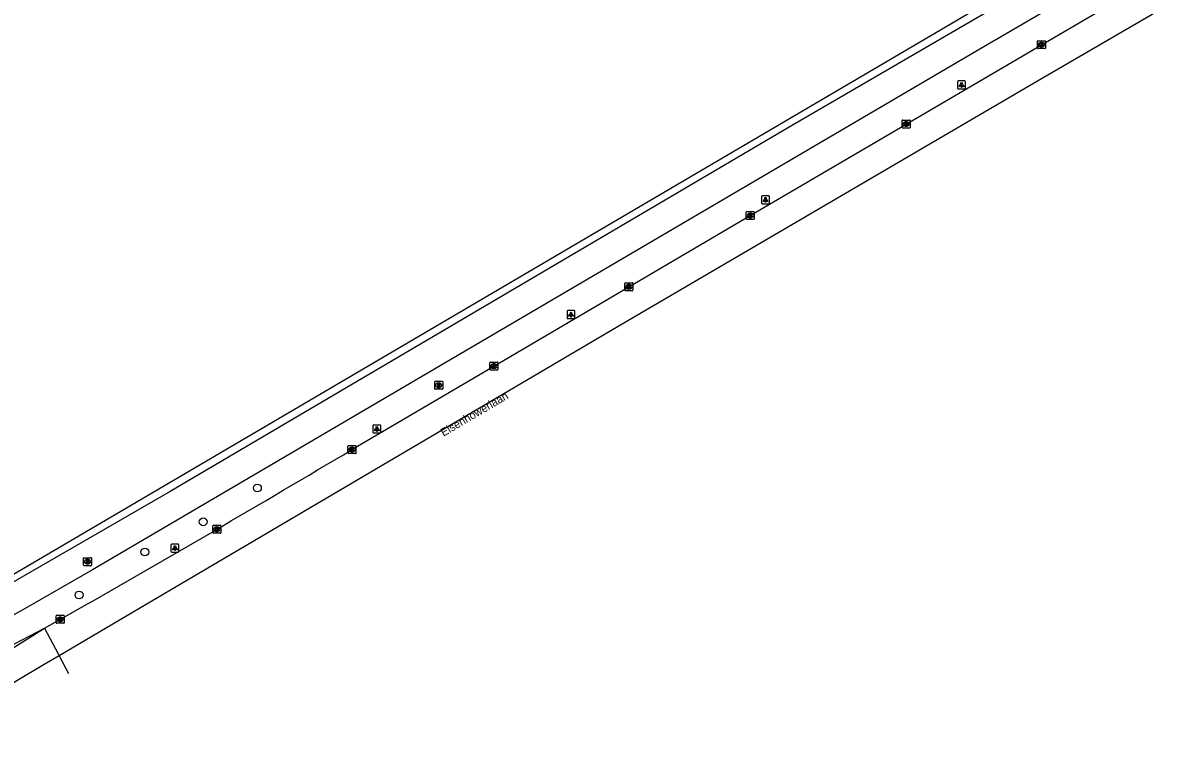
# Model space of a CAD drawing. Extents: x 162417 to 163721, y 384268 to 385416.
# Drawn here: x 163118.6 to 163261.1, y 384365.7 to 384458 of the extents above; entities that cross this region are included whole.
import ezdxf

# ---------------------------------------------------------------- set-up
doc = ezdxf.new("R2010")
doc.units = 0
for name, color, linetype in [('IMGEO_Berm_groen', 7, 'Continuous'), ('IMGEO_Boom', 7, 'Continuous'), ('IMGEO_Fietspad_gesloten', 7, 'Continuous'), ('IMGEO_Hek', 7, 'Continuous'), ('IMGEO_Kolk', 7, 'Continuous'), ('IMGEO_Lichtpunt', 7, 'Continuous'), ('IMGEO_Openbare_ruimte_label', 7, 'Continuous'), ('IMGEO_Rijbaan_regionaal_gesloten', 7, 'Continuous'), ('IMGEO_Rioolput', 7, 'Continuous')]:
    doc.layers.add(name, color=color, linetype=linetype)

msp = doc.modelspace()

# ---------------------------------------------------------------- linework, layer by layer
at = {"layer": 'IMGEO_Berm_groen'}
msp.add_lwpolyline([(163258.75, 384472.14), (163115.25, 384387.77)], dxfattribs=at)
at = {"layer": 'IMGEO_Boom'}
for centre in [(163147.88, 384399.86), (163141.11, 384395.62), (163133.82, 384391.85), (163125.6, 384386.48)]:
    msp.add_circle(centre, 0.489, dxfattribs=at)
at = {"layer": 'IMGEO_Fietspad_gesloten'}
for points in [[(163563.61, 384641.94), (163546.21, 384631.66), (163524.74, 384619.5), (163513.73, 384613.26), (163500, 384605.49), (163486.44, 384597.82), (163417.72, 384558.76), (163354.58, 384522.52), (163336.98, 384512.3), (163315.8, 384500), (163237.63, 384454.43), (163127.28, 384389.63), (163118.59, 384384.62), (163112.28, 384381.2), (163106.55, 384378.4)], [(163345.85, 384521.53), (163335.19, 384515.32), (163308.87, 384500), (163214.31, 384444.96), (163137, 384399.43), (163115.64, 384387.12)]]:
    msp.add_lwpolyline(points, dxfattribs=at)
at = {"layer": 'IMGEO_Hek'}
msp.add_lwpolyline([(163258.75, 384472.14), (163115.25, 384387.77)], dxfattribs=at)
at = {"layer": 'IMGEO_Kolk'}
for p, q in [((163245.34, 384454.86), (163245.34, 384455.71)), ((163245.41, 384455.78), (163246.27, 384455.78)), ((163245.83, 384455.56), (163245.85, 384455.56)), ((163245.85, 384455), (163245.83, 384455)), ((163246.34, 384455.71), (163246.34, 384454.86)), ((163246.27, 384454.78), (163245.41, 384454.78)), ((163228.44, 384444.93), (163228.44, 384445.79)), ((163228.52, 384445.86), (163229.37, 384445.86)), ((163229.37, 384444.86), (163228.52, 384444.86)), ((163228.93, 384445.64), (163228.96, 384445.64)), ((163228.95, 384445.08), (163228.93, 384445.08)), ((163229.44, 384445.79), (163229.44, 384444.93)), ((163208.97, 384433.49), (163208.97, 384434.35)), ((163209.04, 384434.42), (163209.9, 384434.42)), ((163209.9, 384433.42), (163209.04, 384433.42)), ((163209.48, 384433.64), (163209.45, 384433.64)), ((163209.46, 384434.2), (163209.48, 384434.2)), ((163209.97, 384434.35), (163209.97, 384433.49)), ((163193.79, 384424.59), (163193.79, 384425.44)), ((163193.87, 384425.52), (163194.72, 384425.52)), ((163194.28, 384425.29), (163194.31, 384425.29)), ((163194.8, 384425.44), (163194.8, 384424.59)), ((163194.72, 384424.51), (163193.87, 384424.51)), ((163194.3, 384424.74), (163194.28, 384424.74)), ((163176.93, 384414.67), (163176.93, 384415.52)), ((163177, 384415.59), (163177.85, 384415.59)), ((163177.42, 384415.37), (163177.44, 384415.37)), ((163177.93, 384415.52), (163177.93, 384414.67)), ((163177.85, 384414.59), (163177, 384414.59)), ((163177.44, 384414.81), (163177.41, 384414.81)), ((163159.2, 384404.23), (163159.2, 384405.09)), ((163159.28, 384405.16), (163160.13, 384405.16)), ((163159.69, 384404.94), (163159.71, 384404.94)), ((163160.2, 384405.09), (163160.2, 384404.23)), ((163160.13, 384404.16), (163159.28, 384404.16)), ((163159.71, 384404.38), (163159.69, 384404.38)), ((163142.31, 384394.27), (163142.31, 384395.13)), ((163142.39, 384395.2), (163143.24, 384395.2)), ((163142.8, 384394.98), (163142.83, 384394.98)), ((163143.31, 384395.13), (163143.31, 384394.27)), ((163143.24, 384394.2), (163142.39, 384394.2)), ((163142.82, 384394.42), (163142.8, 384394.42)), ((163122.73, 384383.01), (163122.73, 384383.87)), ((163122.81, 384383.94), (163123.66, 384383.94)), ((163123.22, 384383.72), (163123.25, 384383.72)), ((163123.74, 384383.87), (163123.74, 384383.01)), ((163123.66, 384382.94), (163122.81, 384382.94)), ((163123.24, 384383.16), (163123.22, 384383.16))]:
    msp.add_line(p, q, dxfattribs=at)
for points in [[(163245.34, 384454.86), (163245.34, 384455.71)], [(163245.41, 384455.78), (163246.27, 384455.78)], [(163245.66, 384455.48), (163245.78, 384455.48), (163245.78, 384455.33), (163245.91, 384455.48), (163246.08, 384455.48), (163245.93, 384455.33), (163246.08, 384455.08), (163245.93, 384455.08), (163245.85, 384455.25), (163245.78, 384455.18), (163245.78, 384455.08), (163245.66, 384455.08), (163245.66, 384455.48)], [(163246.34, 384455.71), (163246.34, 384454.86)], [(163246.27, 384454.78), (163245.41, 384454.78)], [(163228.44, 384444.93), (163228.44, 384445.79)], [(163228.52, 384445.86), (163229.37, 384445.86)], [(163229.37, 384444.86), (163228.52, 384444.86)], [(163228.76, 384445.56), (163228.89, 384445.56), (163228.89, 384445.41), (163229.02, 384445.56), (163229.18, 384445.56), (163229.03, 384445.41), (163229.19, 384445.16), (163229.03, 384445.16), (163228.95, 384445.32), (163228.89, 384445.26), (163228.89, 384445.16), (163228.76, 384445.16), (163228.76, 384445.56)], [(163229.44, 384445.79), (163229.44, 384444.93)], [(163208.97, 384433.49), (163208.97, 384434.35)], [(163209.04, 384434.42), (163209.9, 384434.42)], [(163209.9, 384433.42), (163209.04, 384433.42)], [(163209.29, 384434.12), (163209.41, 384434.12), (163209.41, 384433.97), (163209.54, 384434.12), (163209.71, 384434.12), (163209.56, 384433.97), (163209.71, 384433.72), (163209.56, 384433.72), (163209.48, 384433.88), (163209.41, 384433.82), (163209.41, 384433.72), (163209.29, 384433.72), (163209.29, 384434.12)], [(163209.97, 384434.35), (163209.97, 384433.49)], [(163193.79, 384424.59), (163193.79, 384425.44)], [(163193.87, 384425.52), (163194.72, 384425.52)], [(163194.11, 384425.21), (163194.24, 384425.21), (163194.24, 384425.06), (163194.37, 384425.21), (163194.53, 384425.21), (163194.39, 384425.06), (163194.54, 384424.81), (163194.39, 384424.81), (163194.3, 384424.98), (163194.24, 384424.91), (163194.24, 384424.81), (163194.11, 384424.81), (163194.11, 384425.21)], [(163194.8, 384425.44), (163194.8, 384424.59)], [(163194.72, 384424.51), (163193.87, 384424.51)], [(163176.93, 384414.67), (163176.93, 384415.52)], [(163177, 384415.59), (163177.85, 384415.59)], [(163177.25, 384415.29), (163177.37, 384415.29), (163177.37, 384415.14), (163177.5, 384415.29), (163177.67, 384415.29), (163177.52, 384415.14), (163177.67, 384414.89), (163177.52, 384414.89), (163177.44, 384415.06), (163177.37, 384414.99), (163177.37, 384414.89), (163177.25, 384414.89), (163177.25, 384415.29)], [(163177.93, 384415.52), (163177.93, 384414.67)], [(163177.85, 384414.59), (163177, 384414.59)], [(163159.2, 384404.23), (163159.2, 384405.09)], [(163159.28, 384405.16), (163160.13, 384405.16)], [(163160.2, 384405.09), (163160.2, 384404.23)], [(163160.13, 384404.16), (163159.28, 384404.16)], [(163159.52, 384404.86), (163159.65, 384404.86), (163159.65, 384404.71), (163159.77, 384404.86), (163159.94, 384404.86), (163159.79, 384404.71), (163159.95, 384404.46), (163159.79, 384404.46), (163159.71, 384404.62), (163159.65, 384404.56), (163159.65, 384404.46), (163159.52, 384404.46), (163159.52, 384404.86)], [(163142.31, 384394.27), (163142.31, 384395.13)], [(163142.39, 384395.2), (163143.24, 384395.2)], [(163143.31, 384395.13), (163143.31, 384394.27)], [(163143.24, 384394.2), (163142.39, 384394.2)], [(163142.63, 384394.9), (163142.76, 384394.9), (163142.76, 384394.75), (163142.89, 384394.9), (163143.05, 384394.9), (163142.91, 384394.75), (163143.06, 384394.5), (163142.91, 384394.5), (163142.82, 384394.67), (163142.76, 384394.6), (163142.76, 384394.5), (163142.63, 384394.5), (163142.63, 384394.9)], [(163122.73, 384383.01), (163122.73, 384383.87)], [(163122.81, 384383.94), (163123.66, 384383.94)], [(163123.05, 384383.64), (163123.18, 384383.64), (163123.18, 384383.49), (163123.31, 384383.64), (163123.47, 384383.64), (163123.33, 384383.49), (163123.48, 384383.24), (163123.33, 384383.24), (163123.24, 384383.41), (163123.18, 384383.34), (163123.18, 384383.24), (163123.05, 384383.24), (163123.05, 384383.64)], [(163123.74, 384383.87), (163123.74, 384383.01)], [(163123.66, 384382.94), (163122.81, 384382.94)]]:
    msp.add_lwpolyline(points, dxfattribs=at)
for centre, start, end in [((163245.42, 384455.71), 91.552, 178.448), ((163245.42, 384455.71), 91.552, 178.448), ((163245.42, 384454.86), 181.552, 268.448), ((163245.42, 384454.86), 181.552, 268.448), ((163246.26, 384455.71), 1.552, 88.448), ((163246.26, 384455.71), 1.552, 88.448), ((163246.26, 384454.86), 271.552, 358.448), ((163246.26, 384454.86), 271.552, 358.448), ((163228.52, 384445.78), 91.552, 178.448), ((163228.52, 384445.78), 91.552, 178.448), ((163228.52, 384444.94), 181.552, 268.448), ((163228.52, 384444.94), 181.552, 268.448), ((163229.37, 384445.78), 1.552, 88.448), ((163229.37, 384445.78), 1.552, 88.448), ((163229.37, 384444.94), 271.552, 358.448), ((163229.37, 384444.94), 271.552, 358.448), ((163209.04, 384434.34), 91.552, 178.448), ((163209.04, 384434.34), 91.552, 178.448), ((163209.04, 384433.5), 181.552, 268.448), ((163209.04, 384433.5), 181.552, 268.448), ((163209.89, 384434.34), 1.552, 88.448), ((163209.89, 384434.34), 1.552, 88.448), ((163209.89, 384433.5), 271.552, 358.448), ((163209.89, 384433.5), 271.552, 358.448), ((163193.87, 384425.44), 91.552, 178.448), ((163193.87, 384425.44), 91.552, 178.448), ((163194.72, 384425.44), 1.552, 88.448), ((163194.72, 384425.44), 1.552, 88.448), ((163193.87, 384424.59), 181.552, 268.448), ((163193.87, 384424.59), 181.552, 268.448), ((163194.72, 384424.59), 271.552, 358.448), ((163194.72, 384424.59), 271.552, 358.448), ((163177, 384415.52), 91.552, 178.448), ((163177, 384415.52), 91.552, 178.448), ((163177.85, 384415.52), 1.552, 88.448), ((163177.85, 384415.52), 1.552, 88.448), ((163177, 384414.67), 181.552, 268.448), ((163177, 384414.67), 181.552, 268.448), ((163177.85, 384414.67), 271.552, 358.448), ((163177.85, 384414.67), 271.552, 358.448), ((163159.28, 384405.08), 91.552, 178.448), ((163159.28, 384405.08), 91.552, 178.448), ((163160.13, 384405.08), 1.552, 88.448), ((163160.13, 384405.08), 1.552, 88.448), ((163159.28, 384404.23), 181.552, 268.448), ((163159.28, 384404.23), 181.552, 268.448), ((163160.13, 384404.23), 271.552, 358.448), ((163160.13, 384404.23), 271.552, 358.448), ((163142.39, 384395.13), 91.552, 178.448), ((163142.39, 384395.13), 91.552, 178.448), ((163143.24, 384395.13), 1.552, 88.448), ((163143.24, 384395.13), 1.552, 88.448), ((163142.39, 384394.28), 181.552, 268.448), ((163142.39, 384394.28), 181.552, 268.448), ((163143.24, 384394.28), 271.552, 358.448), ((163143.24, 384394.28), 271.552, 358.448), ((163122.81, 384383.87), 91.552, 178.448), ((163122.81, 384383.87), 91.552, 178.448), ((163123.66, 384383.87), 1.552, 88.448), ((163123.66, 384383.87), 1.552, 88.448), ((163122.81, 384383.02), 181.552, 268.448), ((163122.81, 384383.02), 181.552, 268.448), ((163123.66, 384383.02), 271.552, 358.448), ((163123.66, 384383.02), 271.552, 358.448)]:
    msp.add_arc(centre, 0.0765, start, end, dxfattribs=at)
for centre, major_axis, ratio, start_param, end_param in [((163245.83, 384455.28), (-0.387, 0.002), 0.722429, 4.712389, 7.853982), ((163245.85, 384455.28), (-0.39, 0.002), 0.717154, 1.570796, 4.712389), ((163228.93, 384445.36), (-0.387, 0.002), 0.722429, 4.712389, 7.853982), ((163228.95, 384445.36), (-0.39, 0.002), 0.717154, 1.570796, 4.712389), ((163209.46, 384433.92), (-0.387, 0.002), 0.722429, 4.712389, 7.853982), ((163209.48, 384433.92), (-0.39, 0.002), 0.717154, 1.570796, 4.712389), ((163194.28, 384425.01), (-0.387, 0.002), 0.722429, 4.712389, 7.853982), ((163194.31, 384425.01), (-0.39, 0.002), 0.717154, 1.570796, 4.712389), ((163177.41, 384415.09), (-0.387, 0.002), 0.722429, 4.712389, 7.853982), ((163177.44, 384415.09), (-0.39, 0.002), 0.717154, 1.570796, 4.712389), ((163159.69, 384404.66), (-0.387, 0.002), 0.722429, 4.712389, 7.853982), ((163159.71, 384404.66), (-0.39, 0.002), 0.717154, 1.570796, 4.712389), ((163142.8, 384394.7), (-0.387, 0.002), 0.722429, 4.712389, 7.853982), ((163142.82, 384394.7), (-0.39, 0.002), 0.717154, 1.570796, 4.712389), ((163123.22, 384383.44), (-0.387, 0.002), 0.722429, 4.712389, 7.853982), ((163123.25, 384383.44), (-0.39, 0.002), 0.717154, 1.570796, 4.712389)]:
    msp.add_ellipse(centre, major_axis=major_axis, ratio=ratio, start_param=start_param, end_param=end_param, dxfattribs=at)
at = {"layer": 'IMGEO_Lichtpunt'}
for p, q in [((163235.36, 384450.64), (163235.36, 384449.84)), ((163235.36, 384450.64), (163235.36, 384449.84)), ((163236.26, 384450.74), (163235.46, 384450.74)), ((163236.26, 384450.74), (163235.46, 384450.74)), ((163236.36, 384449.84), (163236.36, 384450.64)), ((163236.36, 384449.84), (163236.36, 384450.64)), ((163235.46, 384449.74), (163236.26, 384449.74)), ((163235.46, 384449.74), (163236.26, 384449.74)), ((163210.87, 384436.29), (163210.87, 384435.48)), ((163210.87, 384436.29), (163210.87, 384435.48)), ((163211.77, 384436.38), (163210.96, 384436.38)), ((163211.77, 384436.38), (163210.96, 384436.38)), ((163211.87, 384435.48), (163211.87, 384436.29)), ((163211.87, 384435.48), (163211.87, 384436.29)), ((163210.96, 384435.39), (163211.77, 384435.39)), ((163210.96, 384435.39), (163211.77, 384435.39)), ((163187.47, 384422.03), (163186.66, 384422.03)), ((163187.47, 384422.03), (163186.66, 384422.03)), ((163186.57, 384421.93), (163186.57, 384421.12)), ((163186.57, 384421.93), (163186.57, 384421.12)), ((163186.66, 384421.03), (163187.47, 384421.03)), ((163186.66, 384421.03), (163187.47, 384421.03)), ((163187.56, 384421.12), (163187.56, 384421.93)), ((163187.56, 384421.12), (163187.56, 384421.93)), ((163162.31, 384407.64), (163162.31, 384406.83)), ((163162.31, 384407.64), (163162.31, 384406.83)), ((163163.21, 384407.73), (163162.41, 384407.73)), ((163163.21, 384407.73), (163162.41, 384407.73)), ((163162.41, 384406.74), (163163.21, 384406.74)), ((163162.41, 384406.74), (163163.21, 384406.74)), ((163163.31, 384406.83), (163163.31, 384407.64)), ((163163.31, 384406.83), (163163.31, 384407.64)), ((163137.07, 384392.74), (163137.07, 384391.94)), ((163137.07, 384392.74), (163137.07, 384391.94)), ((163137.98, 384392.84), (163137.17, 384392.84)), ((163137.98, 384392.84), (163137.17, 384392.84)), ((163138.07, 384391.94), (163138.07, 384392.74)), ((163138.07, 384391.94), (163138.07, 384392.74)), ((163137.17, 384391.84), (163137.98, 384391.84)), ((163137.17, 384391.84), (163137.98, 384391.84))]:
    msp.add_line(p, q, dxfattribs=at)
for points in [[(163235.74, 384450.31), (163235.77, 384450.28), (163235.59, 384450.02), (163235.55, 384450.05), (163235.74, 384450.31)], [(163235.84, 384450.26), (163235.89, 384450.26), (163235.89, 384449.94), (163235.84, 384449.94), (163235.84, 384450.26)], [(163235.95, 384450.28), (163235.99, 384450.31), (163236.17, 384450.04), (163236.13, 384450.02), (163235.95, 384450.28)], [(163211.24, 384435.95), (163211.28, 384435.92), (163211.09, 384435.66), (163211.06, 384435.69), (163211.24, 384435.95)], [(163211.34, 384435.9), (163211.39, 384435.9), (163211.39, 384435.58), (163211.34, 384435.58), (163211.34, 384435.9)], [(163211.45, 384435.92), (163211.49, 384435.95), (163211.68, 384435.69), (163211.64, 384435.66), (163211.45, 384435.92)], [(163186.94, 384421.59), (163186.98, 384421.57), (163186.79, 384421.3), (163186.75, 384421.33), (163186.94, 384421.59)], [(163187.04, 384421.55), (163187.09, 384421.55), (163187.09, 384421.22), (163187.04, 384421.22), (163187.04, 384421.55)], [(163187.15, 384421.57), (163187.19, 384421.59), (163187.38, 384421.33), (163187.34, 384421.3), (163187.15, 384421.57)], [(163162.69, 384407.3), (163162.73, 384407.27), (163162.54, 384407.01), (163162.5, 384407.04), (163162.69, 384407.3)], [(163162.79, 384407.25), (163162.84, 384407.25), (163162.84, 384406.93), (163162.79, 384406.93), (163162.79, 384407.25)], [(163162.9, 384407.27), (163162.94, 384407.3), (163163.12, 384407.04), (163163.09, 384407.01), (163162.9, 384407.27)], [(163137.45, 384392.41), (163137.49, 384392.38), (163137.3, 384392.12), (163137.26, 384392.14), (163137.45, 384392.41)], [(163137.55, 384392.36), (163137.6, 384392.36), (163137.6, 384392.04), (163137.55, 384392.04), (163137.55, 384392.36)], [(163137.66, 384392.38), (163137.7, 384392.41), (163137.88, 384392.14), (163137.85, 384392.12), (163137.66, 384392.38)]]:
    msp.add_lwpolyline(points, dxfattribs=at)
for centre in [(163235.86, 384450.44), (163211.37, 384436.09), (163187.07, 384421.73), (163162.81, 384407.44), (163137.57, 384392.54)]:
    msp.add_circle(centre, 0.0994, dxfattribs=at)
for centre, start, end in [((163235.46, 384450.64), 90, 180), ((163235.46, 384450.64), 90, 180), ((163236.26, 384450.64), 0, 90), ((163236.26, 384450.64), 0, 90), ((163235.46, 384449.84), 180, 270), ((163235.46, 384449.84), 180, 270), ((163236.26, 384449.84), 270, 0), ((163236.26, 384449.84), 270, 360), ((163210.96, 384436.29), 90, 180), ((163210.96, 384436.29), 90, 180), ((163211.77, 384436.29), 0, 90), ((163211.77, 384436.29), 0, 90), ((163210.96, 384435.48), 180, 270), ((163210.96, 384435.48), 180, 270), ((163211.77, 384435.48), 270, 0), ((163211.77, 384435.48), 270, 360), ((163186.66, 384421.93), 90, 180), ((163186.66, 384421.93), 90, 180), ((163187.47, 384421.93), 0, 90), ((163187.47, 384421.93), 0, 90), ((163186.66, 384421.12), 180, 270), ((163186.66, 384421.12), 180, 270), ((163187.47, 384421.12), 270, 0), ((163187.47, 384421.12), 270, 360), ((163162.41, 384407.64), 90, 180), ((163162.41, 384407.64), 90, 180), ((163162.41, 384406.83), 180, 270), ((163162.41, 384406.83), 180, 270), ((163163.21, 384407.64), 0, 90), ((163163.21, 384407.64), 0, 90), ((163163.21, 384406.83), 270, 0), ((163163.21, 384406.83), 270, 360), ((163137.17, 384392.74), 90, 180), ((163137.17, 384392.74), 90, 180), ((163137.98, 384392.74), 0, 90), ((163137.98, 384392.74), 0, 90), ((163137.17, 384391.94), 180, 270), ((163137.17, 384391.94), 180, 270), ((163137.98, 384391.94), 270, 0), ((163137.98, 384391.94), 270, 360)]:
    msp.add_arc(centre, 0.0946, start, end, dxfattribs=at)
at = {"layer": 'IMGEO_Rijbaan_regionaal_gesloten'}
for points in [[(163698.75, 384708.85), (163688.73, 384703.3), (163649.64, 384681.23), (163618.53, 384663.57), (163596.05, 384651.58), (163528.5, 384613.59), (163468.25, 384579.24), (163409.89, 384545.98), (163340.63, 384506.16), (163340.62, 384506.15), (163245.34, 384450.73), (163192.96, 384420.03), (163150.61, 384395.07), (163132.36, 384384.34), (163123.09, 384378.89)], [(163159.7, 384404.66), (163177.43, 384415.09), (163194.3, 384425.01), (163209.47, 384433.92), (163228.94, 384445.36), (163245.84, 384455.28), (163261.89, 384464.66), (163280.53, 384475.54), (163295.71, 384484.37), (163315.27, 384495.76), (163322.55, 384500), (163332.19, 384505.61), (163338.72, 384509.39), (163350.03, 384515.94), (163367.01, 384525.72), (163384.01, 384535.44), (163401.9, 384545.65), (163418.91, 384555.39), (163436.8, 384565.61), (163459.74, 384578.68), (163476.38, 384588.12)], [(163121.26, 384382.35), (163125.21, 384384.53)], [(162941.48, 384286.06), (162954.03, 384289.76), (162960.83, 384292.29), (162966.43, 384294.61), (162971.28, 384296.91), (163023.96, 384325.75), (163039.5, 384334.56), (163060.95, 384346.6), (163087.01, 384362.04), (163116.02, 384379.05), (163121.26, 384382.35)], [(163121.26, 384382.35), (163122.97, 384379.11), (163123.09, 384378.89)], [(163123.09, 384378.89), (163121.24, 384377.8), (163114.17, 384373.6), (163083.13, 384355.51), (163054.52, 384339), (163012.88, 384315.76), (162974.58, 384294.71), (162965.35, 384289.87), (162959.07, 384286.69), (162954.98, 384285.17), (162947.06, 384282.44), (162946.42, 384282.22), (162935.37, 384279.19), (162924.62, 384276.69), (162917.21, 384275.63), (162908.35, 384275.03), (162883.15, 384273.38)], [(163123.09, 384378.89), (163124.26, 384376.65)]]:
    msp.add_lwpolyline(points, dxfattribs=at)
for centre, radius, start, end in [((162006.92, 386340.25), 2252.87, 299.76107, 300.77679), ((162998.46, 384611.03), 259.57, 294.411, 298.2371)]:
    msp.add_arc(centre, radius, start, end, dxfattribs=at)
at = {"layer": 'IMGEO_Rioolput'}
for p, q in [((163170.03, 384412.27), (163170.03, 384413.13)), ((163170.11, 384413.2), (163170.96, 384413.2)), ((163170.96, 384412.2), (163170.11, 384412.2)), ((163170.52, 384412.98), (163170.55, 384412.98)), ((163170.54, 384412.42), (163170.52, 384412.42)), ((163171.03, 384413.13), (163171.03, 384412.27)), ((163126.15, 384390.21), (163126.15, 384391.07)), ((163126.23, 384391.14), (163127.08, 384391.14)), ((163126.64, 384390.92), (163126.66, 384390.92)), ((163127.15, 384391.07), (163127.15, 384390.21)), ((163127.08, 384390.14), (163126.23, 384390.14)), ((163126.66, 384390.36), (163126.64, 384390.36))]:
    msp.add_line(p, q, dxfattribs=at)
for points in [[(163170.03, 384412.27), (163170.03, 384413.13)], [(163170.11, 384413.2), (163170.96, 384413.2)], [(163170.96, 384412.2), (163170.11, 384412.2)], [(163170.62, 384412.9), (163170.37, 384412.9), (163170.37, 384412.5)], [(163170.37, 384412.5), (163170.49, 384412.5), (163170.49, 384412.66), (163170.51, 384412.66)], [(163170.55, 384412.82), (163170.49, 384412.82), (163170.49, 384412.74)], [(163170.49, 384412.74), (163170.55, 384412.74)], [(163170.55, 384412.63), (163170.62, 384412.5), (163170.76, 384412.5), (163170.7, 384412.63)], [(163171.03, 384413.13), (163171.03, 384412.27)], [(163126.15, 384390.21), (163126.15, 384391.07)], [(163126.23, 384391.14), (163127.08, 384391.14)], [(163126.74, 384390.84), (163126.49, 384390.84), (163126.49, 384390.44)], [(163126.67, 384390.76), (163126.61, 384390.76), (163126.61, 384390.68)], [(163126.61, 384390.68), (163126.66, 384390.68)], [(163127.15, 384391.07), (163127.15, 384390.21)], [(163127.08, 384390.14), (163126.23, 384390.14)], [(163126.49, 384390.44), (163126.61, 384390.44), (163126.61, 384390.6), (163126.62, 384390.6)], [(163126.67, 384390.57), (163126.74, 384390.44), (163126.88, 384390.44), (163126.82, 384390.57)]]:
    msp.add_lwpolyline(points, dxfattribs=at)
for centre, radius, start, end in [((163170.11, 384413.12), 0.0765, 91.552, 178.448), ((163170.11, 384413.12), 0.0765, 91.552, 178.448), ((163170.11, 384412.28), 0.0765, 181.552, 268.448), ((163170.11, 384412.28), 0.0765, 181.552, 268.448), ((163170.5, 384412.61), 0.0533, 26.0293, 88.6989), ((163170.55, 384412.72), 0.0964, 77.0061, 93.1865), ((163170.53, 384412.93), 0.19, 274.7715, 282.9687), ((163170.57, 384412.78), 0.0378, 276.6634, 79.6772), ((163170.62, 384412.79), 0.109, 350.3612, 89.416), ((163170.62, 384412.79), 0.112, 277.5842, 350.9817), ((163170.6, 384412.57), 0.108, 29.5134, 73.7905), ((163170.96, 384413.12), 0.0765, 1.552, 88.448), ((163170.96, 384413.12), 0.0765, 1.552, 88.448), ((163170.96, 384412.28), 0.0765, 271.552, 358.448), ((163170.96, 384412.28), 0.0765, 271.552, 358.448), ((163126.23, 384391.07), 0.0765, 91.552, 178.448), ((163126.23, 384391.07), 0.0765, 91.552, 178.448), ((163126.65, 384390.87), 0.19, 274.7715, 282.9687), ((163126.67, 384390.66), 0.0964, 77.0061, 93.1865), ((163126.69, 384390.72), 0.0378, 276.6634, 79.6772), ((163126.74, 384390.73), 0.109, 350.3612, 89.416), ((163126.74, 384390.73), 0.112, 277.5842, 350.9817), ((163127.08, 384391.07), 0.0765, 1.552, 88.448), ((163127.08, 384391.07), 0.0765, 1.552, 88.448), ((163126.23, 384390.22), 0.0765, 181.552, 268.448), ((163126.23, 384390.22), 0.0765, 181.552, 268.448), ((163126.62, 384390.55), 0.0533, 26.0293, 88.6989), ((163126.72, 384390.51), 0.108, 29.5134, 73.7905), ((163127.08, 384390.22), 0.0765, 271.552, 358.448), ((163127.08, 384390.22), 0.0765, 271.552, 358.448)]:
    msp.add_arc(centre, radius, start, end, dxfattribs=at)
for centre, major_axis, ratio, start_param, end_param in [((163170.52, 384412.7), (-0.387, 0.002), 0.722429, 4.712389, 7.853982), ((163170.54, 384412.7), (-0.39, 0.002), 0.717154, 1.570796, 4.712389), ((163126.64, 384390.64), (-0.387, 0.002), 0.722429, 4.712389, 7.853982), ((163126.66, 384390.64), (-0.39, 0.002), 0.717154, 1.570796, 4.712389)]:
    msp.add_ellipse(centre, major_axis=major_axis, ratio=ratio, start_param=start_param, end_param=end_param, dxfattribs=at)

# ---------------------------------------------------------------- texts
at = {"layer": 'IMGEO_Openbare_ruimte_label'}
msp.add_text('Eisenhowerlaan', height=1, rotation=30.5411, dxfattribs=at).set_placement((163171.14, 384406.26))

doc.saveas('drawing.dxf')
